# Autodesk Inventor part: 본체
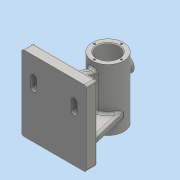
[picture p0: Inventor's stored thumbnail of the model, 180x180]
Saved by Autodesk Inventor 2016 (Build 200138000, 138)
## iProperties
Created: 2022-06
Part Number: 본체
Material: 일반
Document SubType Name: Modeling
Designer: PC-1-3
Density: 1 g/cm^3
Appearance: 기본값
Author: PC-1-3
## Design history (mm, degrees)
sketch "스케치1"
  geometry: L1 (-43, -50)-(43, -50); L2 (43, -50)-(43, 50); L3 (43, 50)-(-43, 50); L4 (-43, 50)-(-43, -50); L5 (-43, -50)-(43, 50); L6 (43, -50)-(-43, 50); 1 further point
  constraints: 12 end point, 2 midpoint, 2 parallel, 1 horizontal, 1 perpendicular
  dimensions: "d0" = 100 distance of L1.end L2.end; "d1" = 86 distance of L1.start L1.end
extrude "돌출1" new body sketch "스케치1" distance "d2" = 15; taper "d3" = 0 deg
sketch "스케치2"
  geometry: L1 (93, 32)-(93, -50); L2 (93, -50)-(72, -50); L3 (72, -50)-(72, 32); L4 (72, 32)-(93, 32); L5 (0, 50)-(15, 50) reference; 1 further point
  constraints: 8 end point, 3 perpendicular, 1 vertical
  dimensions: "d4" = 82 distance of L1.start L1.end; "d5" = 72 distance from line of point (0, 0) L3; "d6" = 42 diameter of L1 L3; "d7" = 100 distance from line of L2.end L5
revolve "회전1" sketch "스케치2" stored, may be unused: angle "d8" = 90 deg
node "작업 평면1"
sketch "스케치5"
  geometry: L1 (43, -57)-(-43, -57) reference; L2 (-35, -57)-(-21, 0); L3 (21, 0)-(35, -57); L4 (-21, 0)-(21, 0); L5 (-35, -57)-(35, -57); A1 r 21 centre (0, 0) between (-21, 0) and (21, 0) reference; A2 r 21 centre (0, 0) between (-21, 0) and (21, 0) reference; 1 further point
  constraints: 8 end point, 4 point on circle, 2 horizontal, 2 point on line, 1 midpoint
  dimensions: "d17" = 8 distance of L1.end L2.start; "d18" = 8 distance of L1.start L3.end
extrude "돌출2" join sketch "스케치5" distance "d19" = 10; taper "d20" = 0 deg
sketch "스케치6"
  geometry: L1 (15, -50)-(15, 50) reference; L2 (15, 35)-(67.913, 15.741); L3 (0, 50)-(15, 50) reference; 1 further point
  constraints: 2 end point, 1 point on line
  dimensions: "d21" = 15 distance from line of L3 L2.start; "d22" = 70 deg angle of L1 L2
feature "리브1" sketch "스케치6" dims "d23" = 1, "d24" = 10, "d25" = 0, "d26" = 0, "d27" = 1, "d28" = 1
sketch "스케치8"
  geometry: C1 r 14.5 at (0, 0); 1 further point
  constraints: 1 centre point
  dimensions: "d30" = 29 diameter of C1
extrude "돌출3" cut sketch "스케치8" distance "d31" = 62; taper "d32" = 0 deg
sketch "스케치9"
  geometry: C1 r 11.5 at (0, 0); 1 further point
  constraints: 1 centre point
  dimensions: "d33" = 23 diameter of C1
extrude "돌출4" cut sketch "스케치9" stored distance "d34" = 62; taper "d35" = 0 deg
node "작업 평면2"
sketch "스케치10"
  geometry: L1 (-21, 32)-(21, 32) reference; L2 (43, -50)-(43, 50) reference; C1 r 11 at (0, 7); 1 further point
  constraints: 1 centre point
  dimensions: "d37" = 25 distance from line of C1.centre L1; "d38" = 22 diameter of C1; "d39" = 43 distance from line of L2 C1.centre
extrude "돌출5" join sketch "스케치10" stored distance "d40" = 62; taper "d41" = 0 deg
sketch "스케치11"
  geometry: C1 r 11 at (0, 0) reference; C2 r 7 at (0, 0); 1 further point
  constraints: 1 centre point, 1 coincident
  dimensions: "d42" = 14 diameter of C2
extrude "돌출6" cut sketch "스케치11" distance "d43" = 4; taper "d44" = 0 deg
sketch "스케치12"
  geometry: L1 (-5, 32)-(-5, -14.677) reference; C1 r 7 at (0, 0) reference; 2 further points
  constraints: 1 coincident
hole "구멍1" sketch "스케치12" at (0, 0) diameter "d45" = 4.917; stored, may be unused: countersink angle "d49" = 82 deg, drill point angle "d51" = 0 deg; dims "d46" = 17, "d47" = 3.023, "d48" = 2, "d50" = 22.1
sketch "스케치13"
  geometry: A1 r 18 centre (0, 0) between (0, 18) and (18, 0); 3 further points
  constraints: 4 point on circle, 1 centre point
  dimensions: "d52" = 36 diameter of A1
hole "구멍2" sketch "스케치13" at (0, 18), (18, 0), (0, -18), (-18, 0) diameter "d53" = 2.459; stored, may be unused: countersink angle "d57" = 82 deg, drill point angle "d59" = 118 deg; dims "d54" = 8, "d55" = 3.023, "d56" = 2, "d58" = 10
sketch "스케치14"
  geometry: A1 r 18 centre (0, 0) between (0, 18) and (18, 0); 3 further points
  constraints: 4 point on circle, 1 centre point
  dimensions: "d60" = 36 diameter of A1
hole "구멍3" sketch "스케치14" at (0, 18), (18, 0), (0, -18), (-18, 0) diameter "d61" = 2.459; stored, may be unused: countersink angle "d65" = 82 deg, drill point angle "d67" = 118 deg; dims "d62" = 8, "d63" = 3.023, "d64" = 2, "d66" = 10
node "작업 평면3"
sketch "스케치15"
  geometry: L1 (27, 24)-(27, 12); L2 (20, 24)-(20, 12); L3 (34, 12)-(34, 24); L4 (43, 50)-(-43, 50) reference; L5 (43, -50)-(43, 50) reference; A1 r 7 centre (27, 24) between (34, 24) and (20, 24); A2 r 7 centre (27, 12) between (20, 12) and (34, 12); 2 further points
  constraints: 8 end point, 4 point on circle, 4 tangent, 2 centre point, 1 midpoint, 1 parallel, 1 vertical
  dimensions: "d69" = 26 distance from line of L4 L1.start; "d70" = 12 distance of L1.start L1.end; "d71" = 7 radius of A2; "d72" = 16 distance from line of L5 point (27, 18)
extrude "돌출7" join sketch "스케치15" stored distance "d73" = 4; taper "d74" = 0 deg
sketch "스케치16"
  geometry: L1 (-27, -24)-(-27, -12); L2 (-23, -24)-(-23, -12); L3 (-31, -12)-(-31, -24); A1 r 7 centre (-27, -12) between (-20, -12) and (-34, -12) reference; A2 r 7 centre (-27, -24) between (-34, -24) and (-20, -24) reference; A3 r 4 centre (-27, -24) between (-31, -24) and (-23, -24); A4 r 4 centre (-27, -12) between (-23, -12) and (-31, -12); 2 further points
  constraints: 8 end point, 4 point on circle, 4 tangent, 2 centre point, 1 midpoint, 1 parallel, 1 vertical
  dimensions: "d75" = 4 radius of A4
extrude "돌출8" cut sketch "스케치16" stored distance "d76" = 4; taper "d77" = 0 deg
chamfer "모따기1" distance "d78" = 1; stored, may be unused: second distance "d79" = 2, angle "d80" = 45 deg
fillet "모깎기1" dims "d81" = 3
fillet "모깎기2" dims "d82" = 3
fillet "모깎기3" dims "d83" = 3
fillet "모깎기4" dims "d84" = 3
fillet "모깎기5" dims "d85" = 1
fillet "모깎기6" dims "d86" = 3
sketch "스케치17"
  geometry: L1 (22.5, 9.5)-(57.5, 9.5); L2 (57.5, 9.5)-(57.5, 2.5); L3 (57.5, 2.5)-(22.5, 2.5); L4 (22.5, 2.5)-(22.5, 9.5); L5 (22.5, 9.5)-(22.5, 2.5); L6 (22.5, 2.5)-(57.5, 2.5); L7 (57.5, 2.5)-(57.5, 9.5); L8 (57.5, 9.5)-(22.5, 9.5); L9 (40, 9.5)-(40, 2.5); L10 (22.5, 6)-(57.5, 6); L11 (83, 0)-(83, 12) reference; L12 (0, 0)-(80, 0) reference; L13 (-3, 12)-(-3, 0) reference; 1 further point
  constraints: 12 end point, 4 midpoint, 3 collinear, 1 perpendicular, 2 other
  dimensions: "d87" = 35 distance of L1.start L1.end; "d88" = 7 distance of L3.end L1.start; "d91" = 6 distance between parallel lines of L12 L10; "d92" = 43 distance between parallel lines of L13 L9
feature "엠보싱1" sketch "스케치17" dims "d0" = 100, "d1" = 86, "d93" = 0.5, "d94" = 0
node "솔리드1"
mirror "대칭1"
node "투영된 루프1"
node "투영된 루프3"
node "투영된 루프4"
other parameters: "d14" = -15, "d36" = 96, "d68" = 18
